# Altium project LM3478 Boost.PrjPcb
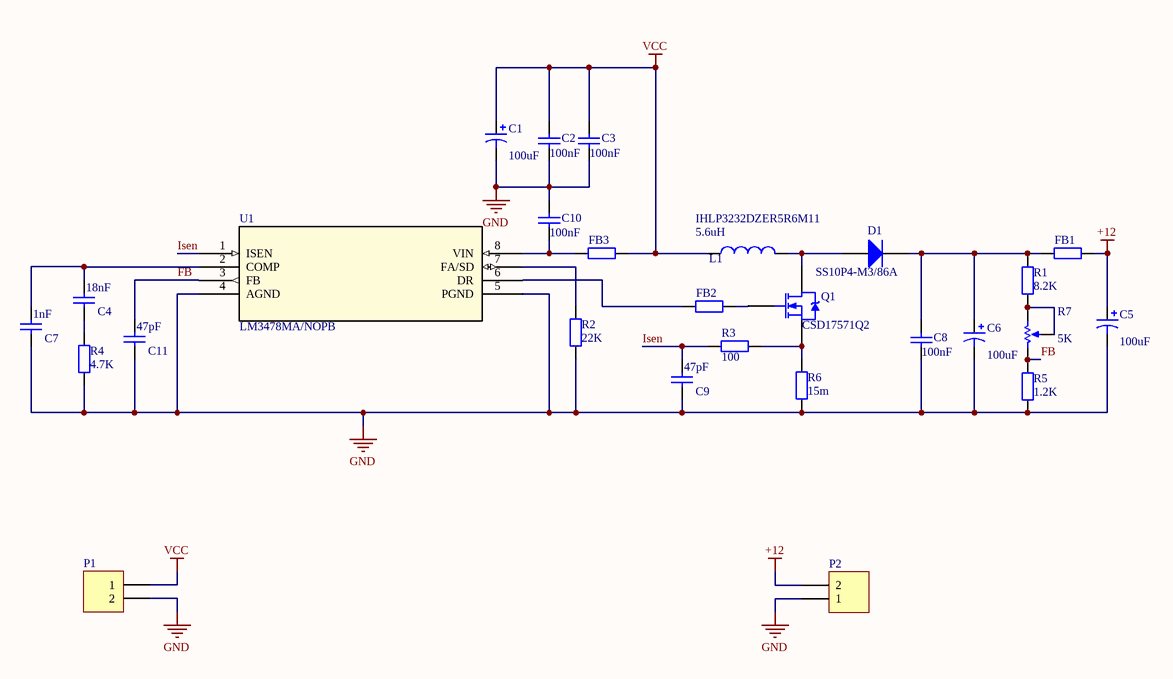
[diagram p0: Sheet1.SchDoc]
1 sheet, 27 parts. Net scope: global (net labels, ports and power ports of the same name join across sheets).
Board file: PCB1.PcbDoc

## Sheet Sheet1.SchDoc
size A4; SheetNumber: 1; SheetTotal: 1

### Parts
C1  value 100uF  [CAP-6.3x5.5]  (hidden comment: 865060343005)
C2  value 100nF  [CAPC1608X08N]  (hidden comment: CL10B104JB8NNNC)
C3  value 100nF  [CAPC1608X08N]  (hidden comment: CL10B104JB8NNNC)
C4  value 18nF  [CAPC1608X08N]  (hidden comment: CC1206JRNPO9BN101)
C5  value 100uF  [CAP-6.3x5.5]  (hidden comment: 865060343005)
C6  value 100uF  [CAP-6.3x5.5]  (hidden comment: 865060343005)
C7  value 1nF  [CAPC1608X08N]  (hidden comment: CC1206JRNPO9BN101)
C8  value 100nF  [CAPC1608X08N]  (hidden comment: CL10B104JB8NNNC)
C9  value 47pF  [CAPC1608X08N]  (hidden comment: CC1206JRNPO9BN101)
C10  value 100nF  [CAPC1608X08N]  (hidden comment: CL10B104JB8NNNC)
C11  value 47pF  [CAPC1608X08N]  (hidden comment: CC1206JRNPO9BN101)
D1  SS10P4-M3/86A  [SS10P4]
FB1  YI453215U101-8R0T  [RES1812 thick]  (value not drawn)
FB2  BLM18HE152SN1D  [RESC1608X06N]  (value not drawn)
FB3  BLM18HE152SN1D  [RESC1608X06N]  (value not drawn)
L1  IHLP3232DZER5R6M11  value 5.6uH  [IHLP3232DZ]
P1  KF2EDGR-5.0-2P & KF2EDGK-5.0-2P  [phonix2]  (value not drawn)
P2  KF2EDGR-5.0-2P & KF2EDGK-5.0-2P  [phonix2]  (value not drawn)
Q1  CSD17571Q2  [DQK0006C]
R1  value 8.2K  [RESC1608X06N]  (hidden comment: 1206W4F1002T5E)
R2  value 22K  [RESC1608X06N]  (hidden comment: 1206W4F1002T5E)
R3  value 100  [RESC1608X06N]  (hidden comment: 1206W4F1002T5E)
R4  value 4.7K  [RESC1608X06N]  (hidden comment: 1206W4F1002T5E)
R5  value 1.2K  [RESC1608X06N]  (hidden comment: 1206W4F1002T5E)
R6  value 15m  [RES1210]  (hidden comment: FRL1210JR015TS)
R7  value 5K  [Multi Turn]  (hidden comment: 3296W-1-502LF)
U1  LM3478MA/NOPB  [M08A]

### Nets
+12: C5.1 FB1.2 P2.2
GND: C1.2 C2.1 C3.1 C5.2 C6.2 C7.1 C8.1 C9.1 C10.2 C11.1 P1.2 P2.1 R2.1 R4.1 R5.2 R6.1 U1.4(AGND) U1.5(PGND)
VCC: C1.1 C2.2 C3.2 FB3.2 L1.1 P1.1
FB: C11.2 R5.1 R7.2(BOT) U1.3(FB)
Isen: C9.2 R3.2 U1.1(ISEN)
NetC4_1: C4.1 R4.2
NetC4_2: C4.2 C7.2 U1.2(COMP)
NetC6_1: C6.1 C8.2 D1.2(K) FB1.1 R1.1
NetC10_1: C10.1 FB3.1 U1.8(VIN)
NetD1_1: D1.1(A) L1.2 Q1.2(D)
NetFB2_1: FB2.1 U1.6(DR)
NetFB2_2: FB2.2 Q1.1(G)
NetQ1_3: Q1.3(S) R3.1 R6.2
NetR1_2: R1.2 R7.1(TOP) R7.3(TAP)
NetR2_2: R2.2 U1.7(FA/SD)

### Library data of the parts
C1 C5 C6 = Cap Pol1: Aluminium Electrolytic Capacitors - SMD WCAP-ASLL 100uF 16V 20% SMD/SMT
C2 C3 C8 C10 = Cap: 50V 100nF X7R ±5% 0603 Ceramic Capacitor
C4 C7 C9 C11 = Cap: 50V 100pF NP0 ±5% 1206 Multilayer Ceramic Capacitors MLCC - SMD/SMT ROHS
D1 = Diode: 40V Independent 480mV@10A 10A TO-277A-3 Single Diodes ROHS
FB1 = Res2: 10mΩ ±25% 100Ω@100MHz 1812 Ferrite Bead; Value: 0.6
FB2 FB3 = Res2: 500mΩ ±25% 1.5kΩ@100MHz 0603 Ferrite Bead; Value: 0.6
L1 = Inductor: 5.6 µH Shielded Molded Inductor 7.4 A 28.6mOhm; Code_IEC: 1005
P1 P2 = Header 2: 15A Green 300V -40℃~+105℃ 5mm Board Side/Socket - Open 2 1 1x2P Right-Angle Pin Through Hole - 15A 320V 5mm Plug 2 1x2P P=5mm Header
Q1 = IRFP143: 30V 22A 29mΩ@4.5V,5A 2.5W 2V 1 N-Channel WSON-6(2x2) Single FETs, MOSFETs ROHS; Note: Pin 2 (drain) is electrically connected to the case metal
R1-R5 = Res2: 0.25W Thick Film Resistors 200V ±100ppm/℃ ±1% 10kΩ 1206 Chip Resistor - Surface Mount ROHS
R6 = Res2: 500mW 15mΩ Thick Film Resistor ±5% 1210 Chip Resistor - Surface Mount ROHS
R7 = RPot: ±10% ±100ppm/℃ 500mW 5kΩ SIP-3P,9.5x4.8mm Trimmer Potentiometer; Sim Note: Enter the Resistance value and the set point into parameter fields.; Set Position: 0.5
U1 = LM3478MANOPB: 2.97~40V Wide Input Range Boost/SEPIC/Flyback DC-DC Controller 8-SOIC -40 to 125; Manufacturer_Name: Texas Instruments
